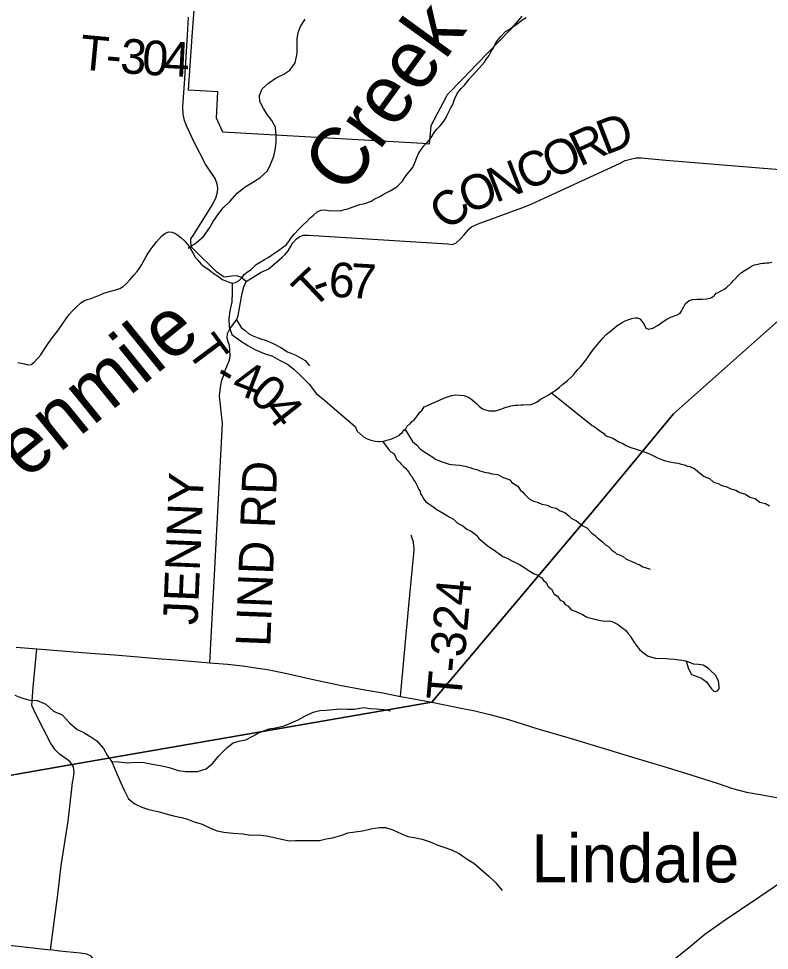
# Model space of a CAD drawing. Extents: x 0 to 39.3, y -3.9 to 22.
# Drawn here: x 3.453 to 4.682, y 15.566 to 17.092 of the extents above; entities that cross this region are included whole.
import ezdxf

# ---------------------------------------------------------------- set-up
doc = ezdxf.new("R2010")
doc.units = 0
for name, color, linetype in [('GM_X_Corporation', 7, 'Continuous'), ('GM_X_County_Road', 7, 'Continuous'), ('GM_X_Minor_Lake', 7, 'Continuous'), ('GM_X_Minor_River', 7, 'Continuous'), ('GM_X_Minor_River_Text', 7, 'Continuous'), ('GM_X_State_Route', 7, 'Continuous'), ('GM_X_Township_Road', 7, 'Continuous'), ('GM_X_Township_Road_Text', 7, 'Continuous'), ('GM_X_Unincorporated_Text', 7, 'Continuous')]:
    doc.layers.add(name, color=color, linetype=linetype)

msp = doc.modelspace()

# ---------------------------------------------------------------- linework, layer by layer
at = {"layer": 'GM_X_Corporation'}
for points in [[(2.8431, 15.7483), (3.5402, 15.8703), (4.1293, 15.9727), (4.3975, 16.29), (4.5253, 16.4446), (4.9525, 16.8243), (5.1896, 16.7753), (5.2324, 16.7664), (5.2611, 16.7603), (5.2717, 16.7593), (5.2788, 16.7568), (5.2938, 16.7523), (5.6057, 16.653), (5.6339, 16.6439), (5.6444, 16.6406), (5.655, 16.638), (5.6693, 16.6354), (5.6908, 16.6325), (5.7298, 16.628), (5.7424, 16.6266), (5.744, 16.6289), (5.8398, 16.7652), (6.0256, 17.0319), (6.2667, 17.3782)], [(4.277, 17.096), (4.257, 17.0728), (4.203, 17.017), (4.1794, 16.9926), (4.1544, 16.9667), (4.1534, 16.9649), (4.1278, 16.9162), (4.1251, 16.8864), (4.1146, 16.8872), (4.0856, 16.8888), (3.8733, 16.9008), (3.8733, 16.9008), (3.787, 16.9056), (3.777, 16.9287), (3.7775, 16.9402), (3.779, 16.9719), (3.7311, 16.9747), (3.7339, 17.0149), (3.7377, 17.0703), (3.7427, 17.1415)], [(4.2376, 14.4362), (5.0728, 15.652), (5.2028, 15.8376), (5.7424, 16.6266), (5.7298, 16.628), (5.6908, 16.6325), (5.6693, 16.6354), (5.655, 16.638), (5.6444, 16.6406), (5.6339, 16.6439), (5.6057, 16.653), (5.2938, 16.7523), (5.2788, 16.7568), (5.2717, 16.7593), (5.2611, 16.7603), (5.2324, 16.7664), (5.1896, 16.7753), (4.9525, 16.8243), (4.5253, 16.4446), (4.3975, 16.29), (4.1293, 15.9727), (3.5402, 15.8703), (2.8431, 15.7483)]]:
    msp.add_lwpolyline(points, dxfattribs=at)
at = {"layer": 'GM_X_County_Road'}
for points in [[(3.543, 15.8618), (3.5424, 15.8668), (3.5404, 15.8698), (3.537, 15.8748), (3.5308, 15.8797), (3.5196, 15.8875), (3.5127, 15.8946), (3.5047, 15.9061), (3.4813, 15.9516), (3.4742, 15.9671), (3.4768, 15.9968), (3.4824, 16.0596)], [(3.6118, 15.3483), (3.5847, 15.5024), (3.5762, 15.5497), (3.5717, 15.5564), (3.5644, 15.5596), (3.5541, 15.5613), (3.5196, 15.5645), (3.5047, 15.5667), (3.517, 15.6576), (3.5226, 15.7048), (3.5336, 15.7776), (3.5401, 15.8304), (3.5407, 15.8407), (3.5424, 15.8487), (3.5435, 15.8578), (3.543, 15.8618)]]:
    msp.add_lwpolyline(points, dxfattribs=at)
at = {"layer": 'GM_X_Minor_Lake'}
for points in [[(4.5459, 16.0398), (4.5494, 16.0271), (4.5545, 16.0179), (4.5708, 16.0119), (4.5794, 16.0053), (4.5842, 15.9988), (4.5875, 15.9941), (4.5913, 15.9907), (4.5943, 15.9898), (4.597, 15.9909), (4.6001, 15.9943), (4.6001, 15.9985), (4.5988, 16.0076), (4.5936, 16.0165), (4.5865, 16.0231), (4.5824, 16.0273), (4.5734, 16.0332)], [(4.5734, 16.0332), (4.5658, 16.0341), (4.5583, 16.0346), (4.5459, 16.0398)]]:
    msp.add_lwpolyline(points, dxfattribs=at)
at = {"layer": 'GM_X_Minor_River'}
for points in [[(3.7327, 16.7171), (3.7305, 16.7161), (3.7432, 16.7246), (3.7556, 16.735), (3.7661, 16.7497), (3.7712, 16.7595), (3.7798, 16.7718), (3.7875, 16.782), (3.7984, 16.7924), (3.8108, 16.8059), (3.8235, 16.8163), (3.8373, 16.8245), (3.8477, 16.8311), (3.8601, 16.8427), (3.8652, 16.8529), (3.8707, 16.8665), (3.8732, 16.8793), (3.8746, 16.8907), (3.8747, 16.9006), (3.8734, 16.9139), (3.8675, 16.9247), (3.8601, 16.9343), (3.8538, 16.9447), (3.8475, 16.9562), (3.847, 16.9661), (3.8517, 16.977), (3.8617, 16.986), (3.8744, 16.9945), (3.8871, 17.0008), (3.8971, 17.0071), (3.9057, 17.0195), (3.909, 17.035), (3.9088, 17.0483), (3.909, 17.0586), (3.9107, 17.0688), (3.9143, 17.079), (3.9221, 17.0906)], [(3.885, 16.7171), (3.8908, 16.7212), (3.8954, 16.7268), (3.8989, 16.7328), (3.9047, 16.7392), (3.9109, 16.7463), (3.9179, 16.7534), (3.9244, 16.7587), (3.9302, 16.7654), (3.9356, 16.7699), (3.9417, 16.7751), (3.9475, 16.7781), (3.9536, 16.7787), (3.9604, 16.7775), (3.9661, 16.777), (3.9729, 16.7773), (3.979, 16.7772), (3.9862, 16.779), (3.992, 16.7805), (4.0007, 16.7834), (4.0065, 16.7859), (4.0114, 16.7874), (4.0175, 16.7884), (4.0229, 16.7899), (4.0298, 16.7928), (4.0347, 16.7962), (4.0443, 16.8006), (4.0497, 16.8039), (4.0547, 16.8065), (4.0612, 16.8098), (4.0665, 16.8128), (4.0719, 16.8165), (4.0769, 16.821), (4.0811, 16.8258), (4.0846, 16.8311), (4.0889, 16.8371), (4.0951, 16.8439), (4.099, 16.8491), (4.1021, 16.8571), (4.1049, 16.8642), (4.1076, 16.871), (4.1107, 16.8759), (4.1165, 16.8834), (4.1219, 16.8887), (4.1254, 16.8935), (4.1293, 16.8988), (4.1332, 16.9052), (4.1378, 16.9108), (4.1432, 16.9164), (4.1479, 16.9221), (4.1521, 16.9288), (4.1545, 16.9337), (4.1572, 16.939), (4.1607, 16.9454), (4.1635, 16.9511), (4.1654, 16.9564), (4.1674, 16.962), (4.1713, 16.97), (4.1775, 16.9771), (4.1829, 16.9827), (4.1864, 16.9876), (4.1907, 16.9928), (4.1961, 16.9988), (4.2065, 17.0101), (4.2115, 17.0153), (4.2154, 17.0206), (4.2189, 17.0258), (4.2231, 17.0315), (4.2259, 17.0371), (4.2301, 17.0439), (4.2329, 17.0499), (4.2368, 17.0559), (4.2426, 17.0627), (4.2499, 17.0706), (4.256, 17.0739), (4.261, 17.0776), (4.2687, 17.0824), (4.2771, 17.0899), (4.284, 17.0936)], [(3.4514, 16.5286), (3.4571, 16.5278), (3.4624, 16.5266), (3.4681, 16.5246), (3.4731, 16.5253), (3.4784, 16.5294), (3.4846, 16.5361), (3.4889, 16.5414), (3.4924, 16.5466), (3.4958, 16.5515), (3.5001, 16.5579), (3.5052, 16.5651), (3.5102, 16.5722), (3.5141, 16.5771), (3.5183, 16.582), (3.5253, 16.5925), (3.5311, 16.6011), (3.5354, 16.6075), (3.5408, 16.6135), (3.5477, 16.6199), (3.5543, 16.6259), (3.5596, 16.6296), (3.5665, 16.6325), (3.5715, 16.6336), (3.5765, 16.6358), (3.5822, 16.638), (3.5872, 16.6402), (3.5921, 16.642), (3.5975, 16.6438), (3.6135, 16.6482), (3.6185, 16.65), (3.6238, 16.6533), (3.6292, 16.6578), (3.635, 16.6638), (3.6419, 16.672), (3.6466, 16.6777), (3.6508, 16.6833), (3.6544, 16.6893), (3.6582, 16.6961), (3.661, 16.701), (3.6649, 16.7074), (3.6684, 16.7127), (3.673, 16.7194), (3.6784, 16.7262), (3.6831, 16.7311), (3.6873, 16.7359), (3.6923, 16.74), (3.6984, 16.7426), (3.7034, 16.7421), (3.7083, 16.7406), (3.7132, 16.7371), (3.7184, 16.7332), (3.7248, 16.7274), (3.7304, 16.7209), (3.7341, 16.7147), (3.7378, 16.7082), (3.7419, 16.7013), (3.746, 16.6963), (3.7516, 16.6898), (3.7569, 16.6855), (3.7626, 16.682), (3.7674, 16.6782), (3.7731, 16.6739), (3.7799, 16.6693), (3.7859, 16.6646), (3.7919, 16.6623), (3.7968, 16.6603), (3.8025, 16.6587), (3.8079, 16.6597), (3.814, 16.6631), (3.8186, 16.6679), (3.8221, 16.6728), (3.8275, 16.6773), (3.8332, 16.6806), (3.8417, 16.6889), (3.8482, 16.6929), (3.8551, 16.6974), (3.8612, 16.7007), (3.8666, 16.7044), (3.872, 16.7074), (3.8789, 16.7126), (3.885, 16.7171)], [(4.6366, 16.6758), (4.6424, 16.6799), (4.6477, 16.6832), (4.6527, 16.6865), (4.6577, 16.6887), (4.6631, 16.6898), (4.6676, 16.6908), (4.6711, 16.6915), (4.6741, 16.6915), (4.6775, 16.6918), (4.6813, 16.6921), (4.6859, 16.6932)], [(4.1193, 16.4573), (4.1518, 16.4712), (4.1572, 16.4727), (4.1618, 16.4745), (4.1686, 16.4755), (4.1758, 16.475), (4.1815, 16.4745), (4.1865, 16.4729), (4.1921, 16.4701), (4.1962, 16.4667), (4.1992, 16.4643), (4.203, 16.4608), (4.2071, 16.4569), (4.2108, 16.4538), (4.215, 16.4515), (4.2233, 16.4494), (4.2271, 16.4494), (4.2336, 16.4496), (4.2405, 16.4518), (4.2466, 16.4536), (4.2508, 16.4554), (4.2538, 16.4561), (4.2588, 16.4576), (4.2622, 16.4583), (4.2668, 16.4586), (4.2699, 16.4589), (4.2752, 16.4592), (4.279, 16.4591), (4.2916, 16.46), (4.2946, 16.4607), (4.2988, 16.4626), (4.3019, 16.4644), (4.3069, 16.4678), (4.3115, 16.4707), (4.3199, 16.4751), (4.3253, 16.4788), (4.3322, 16.4833), (4.3384, 16.4881), (4.3438, 16.493), (4.3484, 16.4967), (4.3515, 16.4993), (4.3573, 16.5045), (4.3612, 16.5087), (4.3647, 16.5128), (4.3686, 16.5173), (4.3728, 16.5218), (4.3771, 16.527), (4.3814, 16.5326), (4.3852, 16.5379), (4.3887, 16.5428), (4.3915, 16.5465), (4.3954, 16.5514), (4.3977, 16.5548), (4.4031, 16.5616), (4.4093, 16.5683), (4.4148, 16.5743), (4.4194, 16.578), (4.4252, 16.5829), (4.4298, 16.5866), (4.434, 16.5899), (4.4409, 16.594), (4.4459, 16.5969), (4.452, 16.5991), (4.457, 16.6006), (4.462, 16.6016), (4.4662, 16.6019), (4.4699, 16.6003), (4.4733, 16.5965), (4.4774, 16.5899), (4.4799, 16.5849), (4.4849, 16.583), (4.4914, 16.5851), (4.5002, 16.5899), (4.5083, 16.5955), (4.514, 16.5996), (4.5217, 16.6032), (4.5309, 16.6065), (4.5359, 16.6094), (4.5382, 16.6125), (4.5398, 16.6158), (4.5417, 16.6189), (4.5449, 16.6253), (4.551, 16.6301), (4.5564, 16.6319), (4.5636, 16.6325), (4.572, 16.6324), (4.5792, 16.633), (4.5849, 16.6341), (4.5884, 16.6355), (4.5915, 16.6378), (4.595, 16.6419), (4.5984, 16.6434), (4.6042, 16.6463), (4.6091, 16.6492), (4.6126, 16.6519), (4.618, 16.6567), (4.6207, 16.6597), (4.6234, 16.6631), (4.6265, 16.6664), (4.6312, 16.6713), (4.6366, 16.6758)], [(3.8025, 16.6587), (3.8026, 16.6426), (3.8016, 16.6278), (3.7987, 16.6134), (3.797, 16.6009), (3.7975, 16.5872), (3.8019, 16.5745), (3.8143, 16.5652), (3.8278, 16.5566), (3.8395, 16.5499), (3.8546, 16.5436), (3.8686, 16.5388), (3.8799, 16.5325), (3.893, 16.5258), (3.9032, 16.5177), (3.9152, 16.5064), (3.9286, 16.4929), (3.9405, 16.4771), (3.9503, 16.4697), (3.9619, 16.46)], [(4.3253, 16.4788), (4.392, 16.4254), (4.395, 16.4238), (4.404, 16.4172), (4.4112, 16.4121), (4.4141, 16.4086), (4.4259, 16.4046), (4.4353, 16.3987), (4.4409, 16.3967), (4.4477, 16.3928), (4.4534, 16.3901), (4.464, 16.3865), (4.4803, 16.3812), (4.4871, 16.3784), (4.4991, 16.3725), (4.5071, 16.369), (4.512, 16.3674), (4.5188, 16.3661), (4.5218, 16.3657), (4.5279, 16.3644), (4.5328, 16.3636), (4.5374, 16.362), (4.5431, 16.3611), (4.5476, 16.3591), (4.5522, 16.3583), (4.5552, 16.3567), (4.5582, 16.3555), (4.5608, 16.354), (4.5646, 16.3505), (4.5676, 16.3481), (4.5755, 16.3419), (4.5842, 16.3387), (4.5905, 16.3329), (4.5981, 16.3305), (4.6041, 16.327), (4.6125, 16.3253), (4.6189, 16.3218), (4.6272, 16.3197), (4.6336, 16.3158), (4.6431, 16.313), (4.6502, 16.3083), (4.6586, 16.3058), (4.6665, 16.3), (4.6755, 16.2976), (4.6823, 16.294)], [(3.9619, 16.46), (4.0041, 16.4235), (4.0056, 16.4197), (4.0078, 16.4158), (4.0126, 16.4115), (4.0175, 16.4069), (4.0235, 16.4037), (4.0269, 16.4025), (4.0296, 16.4013), (4.0364, 16.3997), (4.0421, 16.3992), (4.0448, 16.3992), (4.0497, 16.3999), (4.0524, 16.4006), (4.0555, 16.4013), (4.062, 16.4031), (4.0662, 16.4049), (4.0689, 16.406), (4.0731, 16.4082), (4.0762, 16.4097), (4.0785, 16.4123), (4.0812, 16.4142), (4.0832, 16.4179), (4.0866, 16.4202), (4.0894, 16.4254), (4.0932, 16.4277), (4.0964, 16.4322), (4.0998, 16.4344), (4.1033, 16.4378), (4.1049, 16.4404), (4.1096, 16.4472), (4.1135, 16.4505), (4.1166, 16.4562), (4.1193, 16.4573)], [(4.0843, 16.4187), (4.087, 16.4171), (4.0903, 16.4117), (4.0977, 16.3994), (4.1011, 16.3963), (4.1048, 16.3932), (4.11, 16.3874), (4.116, 16.3827), (4.1209, 16.38), (4.1296, 16.3745), (4.1356, 16.3702), (4.1401, 16.3679), (4.1477, 16.3654), (4.1511, 16.3642), (4.1575, 16.3622), (4.1613, 16.3618), (4.1682, 16.3609), (4.1746, 16.3604), (4.1841, 16.3587), (4.1917, 16.3567), (4.1962, 16.3551), (4.2046, 16.3527), (4.208, 16.3515), (4.2155, 16.3491), (4.2224, 16.3482), (4.2281, 16.3466), (4.2372, 16.3453), (4.2451, 16.3409), (4.2572, 16.3365), (4.2602, 16.3323), (4.2703, 16.326), (4.274, 16.3199), (4.2781, 16.3164), (4.2811, 16.3129), (4.286, 16.3079), (4.289, 16.3055), (4.2958, 16.3016), (4.3033, 16.2996), (4.3094, 16.2964), (4.3181, 16.2948), (4.3249, 16.2916), (4.3332, 16.2899), (4.3396, 16.2856), (4.3472, 16.2828), (4.3536, 16.2774), (4.3577, 16.2739), (4.366, 16.2692), (4.3697, 16.2665), (4.3765, 16.2614), (4.3833, 16.2579), (4.3911, 16.2494), (4.3975, 16.2447), (4.4005, 16.2416), (4.4061, 16.2369), (4.4091, 16.2346), (4.414, 16.2303), (4.4185, 16.2276), (4.4241, 16.2214), (4.429, 16.2179), (4.432, 16.2155), (4.4354, 16.214), (4.4426, 16.2112), (4.4478, 16.2065), (4.4509, 16.2053), (4.4577, 16.2025), (4.4603, 16.2017), (4.4652, 16.199), (4.4686, 16.1978), (4.475, 16.1942), (4.4788, 16.1927), (4.4867, 16.1902)], [(4.0485, 16.3997), (4.0579, 16.3875), (4.062, 16.3825), (4.0669, 16.3794), (4.0691, 16.3759), (4.0717, 16.3702), (4.0769, 16.3648), (4.0791, 16.3621), (4.0829, 16.3582), (4.0862, 16.3555), (4.0915, 16.3493), (4.0944, 16.3443), (4.097, 16.3416), (4.0992, 16.3366), (4.1022, 16.3335), (4.104, 16.3289), (4.1059, 16.3258), (4.1077, 16.3212), (4.1103, 16.3181), (4.111, 16.3135), (4.1128, 16.3108), (4.1165, 16.3051), (4.1191, 16.3012), (4.1244, 16.2973), (4.1293, 16.2938), (4.133, 16.2911), (4.1379, 16.2876), (4.1413, 16.2856), (4.1481, 16.2821), (4.1575, 16.2758), (4.165, 16.2723), (4.1714, 16.2653), (4.1801, 16.2614), (4.1868, 16.2555), (4.1936, 16.2527), (4.2023, 16.2461), (4.2063, 16.2403), (4.2093, 16.238), (4.2157, 16.2326), (4.2187, 16.2302), (4.2255, 16.2252), (4.2307, 16.2217), (4.2356, 16.2178), (4.239, 16.2158), (4.2454, 16.2107), (4.2526, 16.208), (4.2612, 16.2032), (4.2688, 16.2001), (4.2729, 16.1977), (4.2816, 16.1922), (4.2872, 16.1887), (4.297, 16.1825), (4.3035, 16.1804), (4.3061, 16.1774), (4.3095, 16.1758), (4.3121, 16.1715), (4.3162, 16.1688), (4.3199, 16.1619), (4.3251, 16.1576), (4.3296, 16.1495), (4.3352, 16.146), (4.3393, 16.1395), (4.3442, 16.1371), (4.3475, 16.1321), (4.3524, 16.1294), (4.3573, 16.1239), (4.3641, 16.1212), (4.3758, 16.116), (4.3818, 16.1125), (4.3856, 16.1113), (4.3939, 16.1088), (4.3977, 16.108), (4.4087, 16.1055), (4.4155, 16.1051), (4.4194, 16.1054), (4.422, 16.1049), (4.4258, 16.1041), (4.4333, 16.1002), (4.4363, 16.0978), (4.4427, 16.0932), (4.4457, 16.0908), (4.4506, 16.0847), (4.4554, 16.08), (4.4565, 16.0773), (4.461, 16.0696), (4.4643, 16.0654), (4.4695, 16.0588), (4.4759, 16.053), (4.4834, 16.0475), (4.4898, 16.0459), (4.4948, 16.0443), (4.513, 16.044), (4.5187, 16.0435), (4.5263, 16.043), (4.5389, 16.0413), (4.5442, 16.04), (4.5459, 16.0398)], [(3.4467, 15.9841), (3.4576, 15.9798), (3.4712, 15.9757), (3.4833, 15.9751), (3.4973, 15.9692), (3.5096, 15.9579), (3.5243, 15.9516), (3.5362, 15.9385), (3.5486, 15.9276), (3.5587, 15.9232), (3.5711, 15.9154), (3.5809, 15.9092), (3.5917, 15.8968), (3.598, 15.8857), (3.6057, 15.8734), (3.6108, 15.8615), (3.6159, 15.85), (3.6203, 15.8404), (3.6254, 15.8282), (3.6324, 15.8143), (3.6429, 15.8058), (3.6546, 15.8003), (3.6659, 15.7967), (3.6829, 15.7929)], [(3.6057, 15.8734), (3.6069, 15.8753), (3.6167, 15.8747), (3.6304, 15.8729), (3.6452, 15.8742), (3.6585, 15.8736), (3.6747, 15.8703), (3.6846, 15.8686), (3.6993, 15.8656), (3.7141, 15.8608), (3.7258, 15.8591), (3.7459, 15.8587), (3.7597, 15.8631), (3.7708, 15.8728), (3.7805, 15.8844), (3.794, 15.8982), (3.804, 15.9056), (3.8155, 15.9092), (3.825, 15.911), (3.835, 15.9161), (3.8469, 15.9227), (3.8629, 15.9289), (3.8736, 15.9303), (3.8873, 15.9338), (3.8991, 15.9386), (3.9106, 15.9437), (3.9213, 15.9496), (3.9351, 15.9562), (3.9462, 15.9586), (3.9564, 15.9592), (3.9671, 15.9606), (3.9804, 15.9615), (3.9914, 15.9609), (4.0028, 15.9611), (4.0172, 15.9639), (4.0286, 15.9621), (4.0385, 15.9616), (4.051, 15.9602), (4.0619, 15.9581)], [(3.6829, 15.7929), (3.6961, 15.7893), (3.7063, 15.7864), (3.7196, 15.7835), (3.7294, 15.7807), (3.7403, 15.7763), (3.7532, 15.7727), (3.7679, 15.7656), (3.778, 15.762), (3.789, 15.7595), (3.8042, 15.7581), (3.8197, 15.7571), (3.833, 15.7549), (3.8444, 15.7551), (3.8584, 15.7537), (3.869, 15.7516), (3.883, 15.748), (3.8958, 15.7455), (3.9061, 15.7461), (3.9197, 15.7458), (3.9353, 15.7459), (3.9452, 15.7461), (3.9562, 15.7486), (3.9665, 15.7503), (3.9818, 15.7546), (3.9917, 15.7582), (4.0039, 15.7599), (4.0161, 15.762), (4.0294, 15.7652), (4.0439, 15.7672), (4.0533, 15.767), (4.0654, 15.7634), (4.0797, 15.7571), (4.0903, 15.7523), (4.1005, 15.7506), (4.1138, 15.7481), (4.1266, 15.7437), (4.139, 15.7385), (4.1488, 15.7349), (4.1613, 15.7309), (4.1741, 15.7246), (4.1872, 15.7153), (4.1981, 15.7086), (4.2228, 15.6876), (4.2344, 15.6768), (4.2444, 15.6641)]]:
    msp.add_lwpolyline(points, dxfattribs=at)
at = {"layer": 'GM_X_State_Route'}
for points in [[(3.4486, 16.0623), (3.4824, 16.0596), (3.4967, 16.0586), (3.5298, 16.0557), (3.5701, 16.0528), (3.6095, 16.0497), (3.6486, 16.0465), (3.6793, 16.0441), (3.7098, 16.0418), (3.7658, 16.0367), (3.7949, 16.0347), (3.8191, 16.0321), (3.8447, 16.0281), (3.8565, 16.0263), (3.8685, 16.0243), (3.8947, 16.0188), (3.9299, 16.0106), (3.9789, 16.0004), (4.0199, 15.9926), (4.049, 15.9875), (4.078, 15.9816)], [(4.078, 15.9816), (4.1025, 15.9772), (4.1295, 15.9722), (4.1422, 15.9698), (4.1749, 15.9631), (4.1995, 15.9584), (4.2242, 15.9524), (4.255, 15.9439), (4.3031, 15.9285), (4.3521, 15.9144), (4.4117, 15.8968), (4.4634, 15.8805), (4.5074, 15.8675), (4.5537, 15.8532), (4.5983, 15.839), (4.6217, 15.8311), (4.6448, 15.8251), (4.6671, 15.821), (4.6909, 15.8167), (4.7344, 15.8079), (4.782, 15.7981)], [(4.2743, 15.4296), (4.2833, 15.4311), (4.3054, 15.4346), (4.3352, 15.4421), (4.3653, 15.4504), (4.3932, 15.4595), (4.4122, 15.4682), (4.4234, 15.4738), (4.435, 15.481), (4.4487, 15.4895), (4.4623, 15.4992), (4.4766, 15.5093), (4.4931, 15.5243), (4.5057, 15.5343), (4.5214, 15.548), (4.5359, 15.5594), (4.553, 15.5731), (4.5764, 15.5926), (4.6098, 15.6159), (4.6349, 15.6332), (4.6665, 15.6543), (4.6902, 15.6706), (4.7092, 15.6837)]]:
    msp.add_lwpolyline(points, dxfattribs=at)
at = {"layer": 'GM_X_Township_Road'}
for points in [[(3.7658, 16.0367), (3.7866, 16.4285), (3.7819, 16.4733), (3.7835, 16.488), (3.7856, 16.4998), (3.7887, 16.5077), (3.7911, 16.5157), (3.7946, 16.5247), (3.7981, 16.5323), (3.7994, 16.5395), (3.7987, 16.5486), (3.7981, 16.5562), (3.7959, 16.5623), (3.7941, 16.5684), (3.7945, 16.576), (3.7984, 16.5839), (3.8073, 16.5952), (3.8094, 16.5984), (3.81, 16.5993), (3.812, 16.6057), (3.8189, 16.6421), (3.8217, 16.6527), (3.8252, 16.661), (3.8166, 16.6683), (3.8102, 16.6706), (3.8018, 16.67), (3.7893, 16.6686), (3.7844, 16.6717), (3.7765, 16.6771), (3.7414, 16.7121), (3.7358, 16.7175), (3.7347, 16.7251), (3.7348, 16.7312), (3.7394, 16.7383), (3.7681, 16.7835), (3.7754, 16.7978), (3.7782, 16.8077), (3.7787, 16.8145), (3.778, 16.8206), (3.7747, 16.8297), (3.7587, 16.8534), (3.7398, 16.8907), (3.7289, 16.9141), (3.7242, 16.9251), (3.7222, 16.9353), (3.7217, 16.9472), (3.7247, 16.9936), (3.7292, 17.0647), (3.7307, 17.0943)], [(3.8252, 16.661), (3.8501, 16.6764), (3.8578, 16.6796), (3.8616, 16.6814), (3.8675, 16.6862), (3.8845, 16.7009), (3.8892, 16.7053), (3.8939, 16.7117), (3.9018, 16.7244), (3.9077, 16.7314), (3.9131, 16.7351), (3.9192, 16.7372), (3.9272, 16.737), (4.1553, 16.7227), (4.1629, 16.7221), (4.1686, 16.7242), (4.1752, 16.7298), (4.1826, 16.7383), (4.1901, 16.7472), (4.1943, 16.7509), (4.2051, 16.7555), (4.277, 16.7818), (4.2919, 16.7878), (4.3134, 16.7975), (4.4369, 16.8543), (4.4462, 16.8593), (4.4546, 16.8614), (4.4641, 16.8638), (4.4724, 16.864), (4.5123, 16.8602), (4.9528, 16.8237)], [(3.8094, 16.5984), (3.8174, 16.5861), (3.823, 16.5814), (3.8289, 16.5763), (3.8349, 16.5727), (3.8461, 16.5687), (3.8597, 16.5641), (3.8694, 16.5597), (3.8821, 16.5533), (3.8929, 16.5462), (3.9064, 16.5405), (3.922, 16.5317), (3.9288, 16.523)], [(4.078, 15.9816), (4.0918, 16.1307), (4.0977, 16.1932), (4.0998, 16.2152), (4.1004, 16.2232), (4.0992, 16.2342), (4.0957, 16.2457)], [(3.3168, 15.5883), (3.5047, 15.5667)]]:
    msp.add_lwpolyline(points, dxfattribs=at)

# ---------------------------------------------------------------- texts
at = {"layer": 'GM_X_Minor_River_Text'}
for s, height, rotation, p in [('Creek', 0.09472, 54.0084, (3.9893, 16.8001)), ('Tenmile', 0.09471, 39.0098, (3.4042, 16.2867))]:
    msp.add_text(s, height=height, rotation=rotation, dxfattribs=at).set_placement(p)
at = {"layer": 'GM_X_Township_Road_Text'}
for s, height, rotation, p in [('T', 0.0568, 354.605, (3.5512, 17.009)), ('3', 0.0568, 355.71, (3.618, 17.0029)), ('0', 0.0568, 356.5471, (3.6538, 17.0002)), ('4', 0.0568, 357.0657, (3.6893, 16.9981)), ('-', 0.0568, 354.9878, (3.594, 17.005)), ('D', 0.0568, 21.1926, (4.4134, 16.8678)), ('R', 0.0568, 24.5704, (4.3718, 16.8488)), ('O', 0.0568, 24.3831, (4.3261, 16.8281)), ('C', 0.0568, 24.0331, (4.2831, 16.8089)), ('N', 0.0568, 21.2246, (4.2337, 16.7896)), ('O', 0.0568, 20.9931, (4.1868, 16.7716)), ('C', 0.0568, 44.2134, (4.1584, 16.7423)), ('6', 0.0568, 356.6389, (3.9593, 16.6366)), ('T', 0.0568, 43.5119, (3.9345, 16.614)), ('7', 0.0568, 356.6783, (3.9943, 16.6346)), ('-', 0.0568, 19.3803, (3.9432, 16.6297)), ('T', 0.0568, 306.6642, (3.7259, 16.5476)), ('4', 0.0568, 338.9569, (3.7989, 16.481)), ('-', 0.0568, 329.8525, (3.7699, 16.4969)), ('0', 0.0568, 319.6101, (3.8273, 16.471)), ('4', 0.0568, 308.2543, (3.8519, 16.4504)), ('LIND RD', 0.05682, 87.7842, (3.8648, 16.0626)), ('JENNY', 0.05682, 87.6145, (3.7457, 16.0982)), ('T-324', 0.05682, 84.9335, (4.1771, 15.9735))]:
    msp.add_text(s, height=height, rotation=rotation, dxfattribs=at).set_placement(p)
at = {"layer": 'GM_X_Unincorporated_Text'}
msp.add_text('Lindale', height=0.07898, rotation=0, dxfattribs=at).set_placement((4.2922, 15.6772))

doc.saveas('drawing.dxf')
